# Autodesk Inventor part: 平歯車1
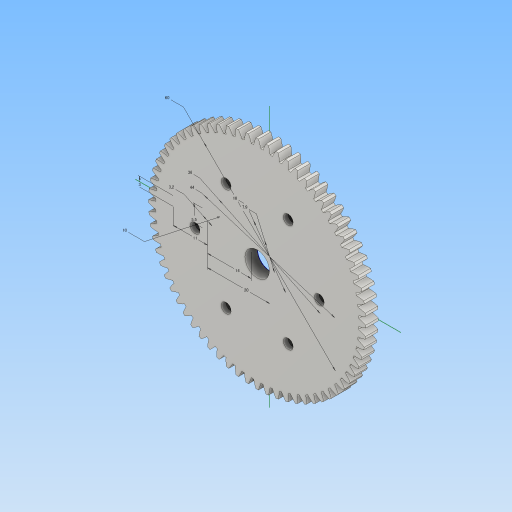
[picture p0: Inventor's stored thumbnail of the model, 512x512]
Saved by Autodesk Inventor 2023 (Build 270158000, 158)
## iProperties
CustomPartVersion: 1
Created: 2024-01
Part Number: 平歯車1
Material: Steel
Document SubType Name: Modeling
Designer: kumagai
Categories: <?xml version="1.0" encoding="UTF-16"?> <MemberInstance><Categories><FamilyTemplate><FamilyTemplateParameter ValueType="xs:double" Id="1" ObjectReferenceKey="da
Density: 1 g/cm^3
Appearance: Steel
Author: kumagai
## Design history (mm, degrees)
sketch "Sketch1"
  geometry: C1 r 35 at (0, 0)
  constraints: 1 centre point
  dimensions: "d0" = 70 diameter of C1 (= da_da)
extrude "Extrusion1" new body sketch "Sketch1" distance "d1" = 4 (= da_b); taper "d2" = 0 deg
workplane "Work Plane2"
sketch "Sketch2"
  geometry: C1 r 35 at (0, 0) reference; C2 r 34 at (0, 0)
  constraints: 1 centre point, 1 coincident
  dimensions: "d3" = 68 diameter of C2 (= da_d)
feature "ピッチ円直径" sketch "Sketch2" dims "d4" = 10, "d5" = 0
workplane "Work Plane8"
workplane "Work Plane9"
feature "平歯車" dims "da_b" = 4, "da_d" = 68 (derived), "da_aw" = 56, "da_da" = 70 (derived), "da_df" = 65.5 (derived), "da_dw" = 68 (derived), angle "da_beta" = 0 deg, "da_lefttooth" = 0, "da_righttooth" = 0
sketch "スケッチ3"
  geometry: L1 (0, 42)-(0, -42) reference; L2 (-43.2, 0)-(42.2, 0) reference; L3 (-15.23, 1.5)-(-6, 1.5); L4 (-6, 1.5)-(-6, -1.5); L5 (-6, -1.5)-(-15.23, -1.5); L6 (-24.77, 1.5)-(-31, 1.5); L7 (-31, 1.5)-(-31, -1.5); L8 (-31, -1.5)-(-24.77, -1.5); L9 (-16.825, 0)-(-18.412, -2.75); L10 (-18.412, -2.75)-(-21.588, -2.75); L11 (-21.588, -2.75)-(-23.175, 0); L12 (-23.175, 0)-(-21.588, 2.75); L13 (-21.588, 2.75)-(-18.412, 2.75); L14 (-18.412, 2.75)-(-16.825, 0); C1 r 3.95 at (0, 0); C2 r 30 at (0, 0); C3 r 1.6 at (-20, 0); C4 r 9 at (0, 0); C5 r 18 at (0, 0); C6 r 22 at (0, 0); A1 r 5 centre (-20, 0) between (-15.23, 1.5) and (-15.23, -1.5); 6 further points
  constraints: 24 end point, 7 centre point, 7 coincident, 6 point on line, 4 point on circle, 2 vertical, 1 horizontal, 14 other
  dimensions: "d49" = 60 diameter of C2; "d50" = 20 distance from line of L1 C3.centre; "d51" = 10 diameter of A1; "d52" = 7.9 diameter of C1; "d53" = 18 diameter of C4; "d54" = 36 diameter of C5; "d55" = 44 diameter of C6; "d56" = 3.2 diameter of C3; "d57" = 3 distance between parallel lines of L8 L6; "d58" = 14 distance from line of L4 C3.centre; "d59" = 11 distance from line of C3.centre L7; "d86" = 5.5 distance between parallel lines of L10 L13
extrude "押し出し2" cut sketch "スケッチ3" distance "d60" = 1; taper "d61" = 0 deg
extrude "押し出し3" cut sketch "スケッチ3" extent not by distance; stored distance "d62" = 3; taper "d63" = 0 deg
extrude "押し出し4" join sketch "スケッチ3" distance "d64" = 4; taper "d65" = 0 deg
extrude "押し出し5" cut sketch "スケッチ3" extent not by distance; stored distance "d66" = 0; taper "d67" = 0 deg
pattern_circular "円形状パターン2" dims angle "d75" = 360 deg
chamfer "面取り1" distance "d77" = 0.8; stored, may be unused: second distance "d78" = 2, angle "d79" = 45 deg
extrude "押し出し6" cut sketch "スケッチ3" distance "d69" = 2.5; taper "d70" = 0 deg
pattern_circular "円形状パターン3" dims angle "d81" = 360 deg
chamfer "面取り2" distance "d83" = 0.5; stored, may be unused: second distance "d84" = 2, angle "d85" = 45 deg
body "Solid1"
body "Srf1"
other parameters: "d16" = 56 (= da_aw), "d17" = 0, "d34" = 0.462 (computed from da_z), "d39" = 0, "d41" = 0, "d43" = 56 (= da_aw), "d46" = 56 (= da_aw), "d47" = 0, "d48" = 0
